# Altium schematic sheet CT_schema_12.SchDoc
size 147 x 119 mm
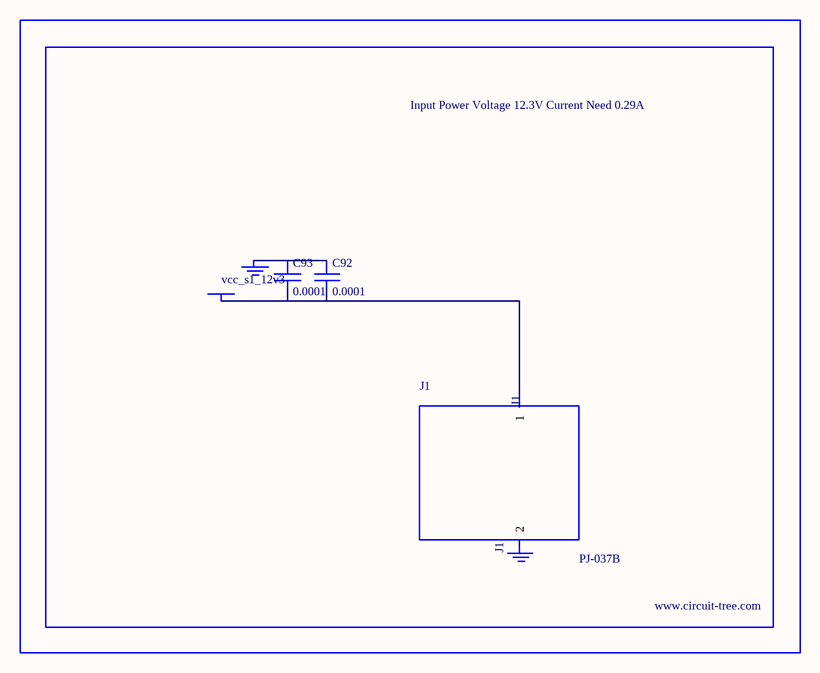
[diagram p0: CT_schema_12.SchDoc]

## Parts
BORDER11  (no value)
C92  0.0001  [EXV-9H]
C93  0.0001  [EXV-9H]
GND_INSTANCE_11_0  (no value)
GND_INSTANCE_11_1  (no value)
J1  PJ-037B  [PJ-037B_PACKAGE]
POWER_INSTANCE_11_0  vcc_s1_12v3

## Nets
NetC92_1: C92.1 C93.1 GND_INSTANCE_11_0.0(GND)
NetC92_2: C92.2 C93.2 J1.1 POWER_INSTANCE_11_0.0(PWR)

Not connected (* = marked no-connect by the designer): GND_INSTANCE_11_1 0(GND); J1 2

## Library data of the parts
BORDER11 = BORDER_PAGE11
C92 C93 = EDK107M035A9HAA
GND_INSTANCE_11_0 GND_INSTANCE_11_1 = GND
POWER_INSTANCE_11_0 = PWR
